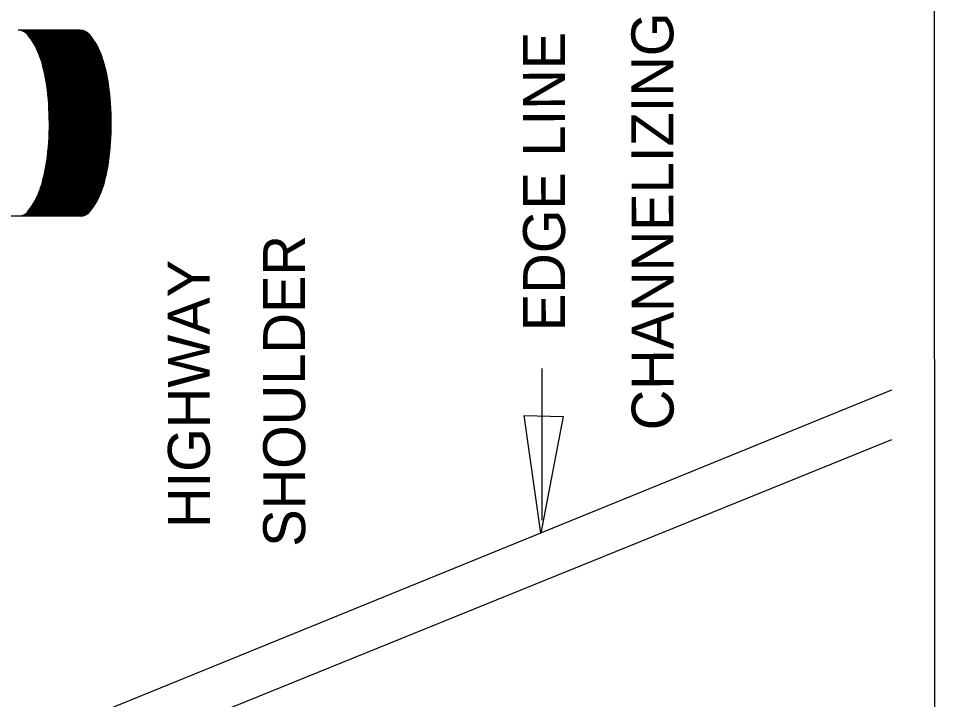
# Model space of a CAD drawing. Extents: x 612.5 to 619.9, y 611 to 621.1.
# Drawn here: x 617.928 to 619.239, y 618.299 to 619.273 of the extents above; entities that cross this region are included whole.
import ezdxf

# ---------------------------------------------------------------- set-up
doc = ezdxf.new("R2010")
doc.units = 0
for name, color, linetype in [('DETL-DIMS', 7, 'Continuous'), ('DETL-LINE', 7, 'Continuous'), ('DETL-NOTE', 7, 'Continuous')]:
    doc.layers.add(name, color=color, linetype=linetype)

msp = doc.modelspace()

# ---------------------------------------------------------------- linework, layer by layer
at = {"layer": 'DETL-DIMS'}
for p, q in [((619.2373, 620.4561), (619.239, 617.9625)), ((618.6772, 618.7725), (618.6774, 618.5556))]:
    msp.add_line(p, q, dxfattribs=at)
msp.add_lwpolyline([(618.6519, 618.7051), (618.7077, 618.7036), (618.6756, 618.5369)], close=True, dxfattribs=at)
at = {"layer": 'DETL-LINE'}
for p, q in [((618.0171, 619.2561), (617.9285, 619.2561)), ((617.9297, 619.2561), (617.9297, 619.256)), ((617.9313, 619.2561), (617.9311, 619.2558)), ((617.9328, 619.2561), (617.9324, 619.2556)), ((617.9344, 619.2561), (617.9336, 619.2553)), ((617.936, 619.2561), (617.9348, 619.2549)), ((617.9376, 619.2561), (617.9359, 619.2544)), ((617.9391, 619.2561), (617.937, 619.2539)), ((617.9407, 619.2561), (617.9379, 619.2533)), ((617.9423, 619.2561), (617.9389, 619.2527)), ((617.9438, 619.2561), (617.9397, 619.252)), ((617.9454, 619.2561), (617.9406, 619.2512)), ((617.947, 619.2561), (617.9414, 619.2504)), ((617.9486, 619.2561), (617.9421, 619.2496)), ((617.9501, 619.2561), (617.9428, 619.2488)), ((617.9517, 619.2561), (617.9435, 619.2479)), ((617.9532, 619.2561), (617.9442, 619.247)), ((617.9548, 619.2561), (617.9448, 619.246)), ((617.9564, 619.2561), (617.9455, 619.2452)), ((617.9579, 619.2561), (617.9461, 619.2442)), ((617.9594, 619.2561), (617.9468, 619.2434)), ((617.961, 619.2561), (617.9474, 619.2424)), ((617.9626, 619.2561), (617.948, 619.2414)), ((617.9642, 619.2561), (617.9486, 619.2406)), ((617.9657, 619.2561), (617.9492, 619.2396)), ((617.9673, 619.2561), (617.9498, 619.2386)), ((617.9689, 619.2561), (617.9505, 619.2376)), ((617.9704, 619.2561), (617.9511, 619.2366)), ((617.972, 619.2561), (617.9516, 619.2357)), ((617.9736, 619.2561), (617.9522, 619.2346)), ((617.9752, 619.2561), (617.9527, 619.2336)), ((617.9767, 619.2561), (617.9532, 619.2326)), ((617.9783, 619.2561), (617.9538, 619.2316)), ((617.9798, 619.2561), (617.9543, 619.2305)), ((617.9814, 619.2561), (617.9548, 619.2295)), ((617.983, 619.2561), (617.9554, 619.2284)), ((617.9846, 619.2561), (617.9559, 619.2274)), ((617.9861, 619.2561), (617.9563, 619.2262)), ((617.9877, 619.2561), (617.9568, 619.2252)), ((617.9893, 619.2561), (617.9573, 619.2241)), ((617.9908, 619.2561), (617.9577, 619.223)), ((617.9923, 619.2561), (617.9581, 619.2218)), ((617.9939, 619.2561), (617.9586, 619.2207)), ((617.9954, 619.2561), (617.959, 619.2196)), ((617.997, 619.2561), (617.9594, 619.2184)), ((617.9986, 619.2561), (617.9598, 619.2173)), ((618.0002, 619.2561), (617.9602, 619.216)), ((618.0017, 619.2561), (617.9606, 619.2148)), ((618.0033, 619.2561), (617.961, 619.2137)), ((618.0049, 619.2561), (617.9614, 619.2125)), ((618.0064, 619.2561), (617.9617, 619.2112)), ((618.008, 619.2561), (617.962, 619.2101)), ((618.0096, 619.2561), (617.9624, 619.2089)), ((618.0112, 619.2561), (617.9628, 619.2077)), ((618.0127, 619.2561), (617.9631, 619.2065)), ((618.0143, 619.2561), (617.9634, 619.2052)), ((618.0159, 619.2561), (617.9638, 619.204)), ((618.0174, 619.2561), (617.9642, 619.2027)), ((618.0189, 619.256), (617.9644, 619.2015)), ((618.0202, 619.2558), (617.9648, 619.2003)), ((618.0215, 619.2556), (617.9651, 619.199)), ((618.0228, 619.2552), (617.9654, 619.1978)), ((618.0239, 619.2548), (617.9656, 619.1964)), ((618.0249, 619.2542), (617.966, 619.1952)), ((618.026, 619.2537), (617.9662, 619.1939)), ((618.027, 619.2531), (617.9665, 619.1926)), ((618.0278, 619.2524), (617.9668, 619.1913)), ((618.0287, 619.2517), (617.967, 619.19)), ((618.0295, 619.2509), (617.9673, 619.1887)), ((618.0302, 619.2502), (617.9676, 619.1874)), ((618.031, 619.2493), (617.9678, 619.186)), ((618.0316, 619.2484), (617.968, 619.1847)), ((618.0324, 619.2475), (617.9682, 619.1834)), ((618.033, 619.2467), (617.9684, 619.182)), ((618.0336, 619.2458), (617.9687, 619.1806)), ((618.0344, 619.2448), (617.9689, 619.1792)), ((618.035, 619.244), (617.969, 619.178)), ((618.0357, 619.243), (617.9693, 619.1766)), ((618.0363, 619.242), (617.9695, 619.1752)), ((618.0369, 619.2411), (617.9696, 619.1738)), ((618.0375, 619.2401), (617.9698, 619.1724)), ((618.0381, 619.2392), (617.97, 619.171)), ((618.0387, 619.2382), (617.9702, 619.1696)), ((618.0393, 619.2372), (617.9704, 619.1682)), ((618.0398, 619.2363), (617.9705, 619.1668)), ((618.0404, 619.2352), (617.9706, 619.1654)), ((618.041, 619.2343), (617.9708, 619.164)), ((618.0415, 619.2332), (617.971, 619.1625)), ((618.0421, 619.2322), (617.971, 619.1611)), ((618.0426, 619.2312), (617.9712, 619.1596)), ((618.0432, 619.2302), (617.9713, 619.1582)), ((618.0436, 619.229), (617.9715, 619.1568)), ((618.0441, 619.228), (617.9716, 619.1554)), ((618.0446, 619.227), (617.9716, 619.1539)), ((618.0451, 619.2258), (617.9718, 619.1525)), ((618.0456, 619.2248), (617.9719, 619.151)), ((618.046, 619.2236), (617.972, 619.1495)), ((618.0465, 619.2225), (617.9721, 619.148)), ((618.0469, 619.2214), (617.9722, 619.1466)), ((618.0474, 619.2202), (617.9723, 619.1451)), ((618.0478, 619.2191), (617.9724, 619.1436)), ((618.0482, 619.218), (617.9724, 619.1421)), ((618.0486, 619.2168), (617.9725, 619.1406)), ((618.049, 619.2156), (617.9725, 619.1391)), ((618.0494, 619.2144), (617.9726, 619.1376)), ((618.0497, 619.2133), (617.9727, 619.1361)), ((618.05, 619.212), (617.9727, 619.1346)), ((618.0505, 619.2108), (617.9728, 619.133)), ((618.0508, 619.2096), (617.9728, 619.1316)), ((618.0512, 619.2084), (617.9729, 619.13)), ((618.0515, 619.2072), (617.9729, 619.1284)), ((618.0519, 619.2059), (617.9729, 619.1268)), ((618.0549, 619.1934), (617.9727, 619.111)), ((618.0552, 619.1921), (617.9727, 619.1094)), ((618.0544, 619.196), (617.9728, 619.1143)), ((618.0547, 619.1947), (617.9728, 619.1127)), ((618.0522, 619.2047), (617.9729, 619.1254)), ((618.0525, 619.2035), (617.9729, 619.1238)), ((618.0528, 619.2023), (617.9729, 619.1222)), ((618.0532, 619.201), (617.9729, 619.1206)), ((618.0534, 619.1998), (617.9729, 619.1191)), ((618.0538, 619.1985), (617.9729, 619.1175)), ((618.0541, 619.1972), (617.9729, 619.1158)), ((618.0574, 619.1801), (617.9719, 619.0946)), ((618.0571, 619.1815), (617.972, 619.0962)), ((618.057, 619.1828), (617.9721, 619.0979)), ((618.0567, 619.1842), (617.9722, 619.0996)), ((618.056, 619.1882), (617.9724, 619.1045)), ((618.0562, 619.1868), (617.9724, 619.1028)), ((618.0565, 619.1855), (617.9724, 619.1012)), ((618.0557, 619.1894), (617.9725, 619.1062)), ((618.0554, 619.1908), (617.9726, 619.1078)), ((618.0591, 619.1662), (617.9702, 619.0773)), ((618.059, 619.1676), (617.9704, 619.079)), ((618.0588, 619.169), (617.9707, 619.0808)), ((618.0586, 619.1704), (617.9709, 619.0825)), ((618.0584, 619.1718), (617.971, 619.0843)), ((618.0582, 619.1732), (617.9712, 619.086)), ((618.0581, 619.1746), (617.9713, 619.0878)), ((618.0579, 619.176), (617.9715, 619.0894)), ((618.0577, 619.1774), (617.9716, 619.0912)), ((618.0576, 619.1787), (617.9717, 619.0928)), ((618.0604, 619.1534), (617.968, 619.0608)), ((618.0602, 619.1548), (617.9682, 619.0628)), ((618.0601, 619.1562), (617.9686, 619.0646)), ((618.06, 619.1577), (617.9689, 619.0665)), ((618.0598, 619.1591), (617.9691, 619.0683)), ((618.0597, 619.1606), (617.9694, 619.0701)), ((618.0596, 619.162), (617.9696, 619.0719)), ((618.0594, 619.1634), (617.9698, 619.0737)), ((618.0593, 619.1649), (617.9701, 619.0755)), ((618.0611, 619.14), (617.9641, 619.0428)), ((618.061, 619.1415), (617.9646, 619.045)), ((618.061, 619.1431), (617.9651, 619.047)), ((618.0609, 619.1446), (617.9656, 619.049)), ((618.0608, 619.146), (617.966, 619.051)), ((618.0607, 619.1475), (617.9664, 619.0531)), ((618.0606, 619.1489), (617.9668, 619.0551)), ((618.0605, 619.1504), (617.9673, 619.057)), ((618.0604, 619.1519), (617.9676, 619.0589)), ((618.0615, 619.1278), (617.9583, 619.0246)), ((618.0614, 619.1294), (617.9593, 619.0271)), ((618.0614, 619.131), (617.96, 619.0294)), ((618.0614, 619.1324), (617.9608, 619.0318)), ((618.0613, 619.134), (617.9615, 619.034)), ((618.0613, 619.1355), (617.9622, 619.0363)), ((618.0612, 619.137), (617.9628, 619.0385)), ((618.0612, 619.1385), (617.9634, 619.0407)), ((618.0614, 619.1152), (617.9367, 618.9904)), ((618.0614, 619.1137), (617.9382, 618.9904)), ((618.0614, 619.1168), (617.9448, 619.0001)), ((618.0615, 619.1185), (617.9484, 619.0053)), ((618.0615, 619.12), (617.951, 619.0094)), ((618.0615, 619.1216), (617.953, 619.013)), ((618.0615, 619.1232), (617.9546, 619.0162)), ((618.0615, 619.1248), (617.956, 619.0191)), ((618.0615, 619.1263), (617.9573, 619.0219)), ((618.0613, 619.112), (617.9397, 618.9904)), ((618.0613, 619.1104), (617.9413, 618.9904)), ((618.0612, 619.1088), (617.9429, 618.9904)), ((618.0611, 619.1071), (617.9444, 618.9904)), ((618.0611, 619.1056), (617.946, 618.9904)), ((618.061, 619.1039), (617.9476, 618.9904)), ((618.061, 619.1022), (617.9492, 618.9904)), ((618.0609, 619.1006), (617.9507, 618.9904)), ((618.0608, 619.0989), (617.9523, 618.9904)), ((618.0606, 619.0973), (617.9539, 618.9904)), ((618.0605, 619.0955), (617.9554, 618.9904)), ((618.0604, 619.0939), (617.957, 618.9904)), ((618.0602, 619.0922), (617.9586, 618.9904)), ((618.0602, 619.0905), (617.9602, 618.9904)), ((618.06, 619.0888), (617.9617, 618.9904)), ((618.0598, 619.0871), (617.9633, 618.9904)), ((618.0596, 619.0853), (617.9648, 618.9904)), ((618.0596, 619.0836), (617.9664, 618.9904)), ((618.0594, 619.0818), (617.968, 618.9904)), ((618.0591, 619.0801), (617.9696, 618.9904)), ((618.059, 619.0784), (617.9711, 618.9904)), ((618.0588, 619.0765), (617.9726, 618.9904)), ((618.0585, 619.0748), (617.9742, 618.9904)), ((618.0583, 619.073), (617.9758, 618.9904)), ((618.0581, 619.0712), (617.9773, 618.9904)), ((618.0578, 619.0694), (617.9789, 618.9904)), ((618.0576, 619.0675), (617.9804, 618.9904)), ((618.0573, 619.0657), (617.982, 618.9904)), ((618.057, 619.0639), (617.9836, 618.9904)), ((618.0568, 619.062), (617.9852, 618.9904)), ((618.0564, 619.0601), (617.9867, 618.9904)), ((618.0561, 619.0582), (617.9883, 618.9904)), ((618.0556, 619.0562), (617.9899, 618.9904)), ((618.0553, 619.0543), (617.9914, 618.9904)), ((618.0548, 619.0523), (617.993, 618.9904)), ((618.0544, 619.0503), (617.9946, 618.9904)), ((618.054, 619.0483), (617.9962, 618.9904)), ((618.0534, 619.0462), (617.9977, 618.9904)), ((618.0529, 619.0441), (617.9993, 618.9904)), ((618.0523, 619.042), (618.0009, 618.9904)), ((618.0518, 619.0398), (618.0024, 618.9904)), ((618.0512, 619.0376), (618.004, 618.9904)), ((618.0505, 619.0354), (618.0056, 618.9904)), ((618.0498, 619.0331), (618.007, 618.9904)), ((618.0491, 619.0308), (618.0086, 618.9904)), ((618.0483, 619.0285), (618.0102, 618.9904)), ((618.0474, 619.026), (618.0118, 618.9904)), ((618.0464, 619.0235), (618.0133, 618.9904)), ((618.0454, 619.0208), (618.0149, 618.9904)), ((618.044, 619.0179), (618.0165, 618.9904)), ((618.0426, 619.0149), (618.018, 618.9904)), ((618.0407, 619.0115), (618.0198, 618.9905)), ((618.0386, 619.0077), (618.0218, 618.991)), ((618.0357, 619.0033), (618.0242, 618.9918)), ((618.0311, 618.9972), (618.028, 618.994)), ((617.9286, 618.9903), (617.8402, 618.9903)), ((618.0173, 618.9904), (617.9286, 618.9903)), ((617.9305, 618.9904), (617.9304, 618.9903)), ((617.9323, 618.9907), (617.932, 618.9903)), ((617.9345, 618.9913), (617.9336, 618.9903)), ((617.9374, 618.9926), (617.9351, 618.9903)), ((614.1712, 616.7038), (619.1778, 618.7417)), ((612.9704, 616.1534), (619.1778, 618.671))]:
    msp.add_line(p, q, dxfattribs=at)
for centre, radius, start, end in [((617.9285, 619.2385), 0.0175, 38.8648, 90.0399), ((617.861, 619.1841), 0.1042, 18.4748, 38.8648), ((618.0171, 619.2386), 0.0175, 38.8648, 90.0399), ((617.9496, 619.1842), 0.1042, 18.4748, 38.8648), ((617.751, 619.1474), 0.2202, 7.9011, 18.4748), ((617.8395, 619.1474), 0.2202, 7.9011, 18.4748), ((617.575, 619.1229), 0.3979, 0.0399, 7.9011), ((617.6635, 619.123), 0.3979, 0.0399, 7.9011), ((617.575, 619.1229), 0.3979, 352.1787, 0.0399), ((617.6635, 619.123), 0.3979, 352.1787, 0.0399), ((617.751, 619.0988), 0.2202, 341.6049, 352.1787), ((617.8396, 619.0988), 0.2202, 341.6049, 352.1787), ((617.8611, 619.0621), 0.1042, 321.2149, 341.6049), ((617.9497, 619.0622), 0.1042, 321.2149, 341.6049), ((617.9287, 619.0078), 0.0175, 270.0398, 321.2149), ((618.0173, 619.0079), 0.0175, 270.0398, 321.2149)]:
    msp.add_arc(centre, radius, start, end, dxfattribs=at)

# ---------------------------------------------------------------- texts
at = {"layer": 'DETL-NOTE'}
for s, p in [('CHANNELIZING DRUM', (618.8657, 618.684)), ('EDGE LINE', (618.7105, 618.8258)), ('SHOULDER', (618.3388, 618.5174)), ('HIGHWAY', (618.2025, 618.5443))]:
    msp.add_text(s, height=0.06, rotation=90.0399, dxfattribs=at).set_placement(p)

doc.saveas('drawing.dxf')
